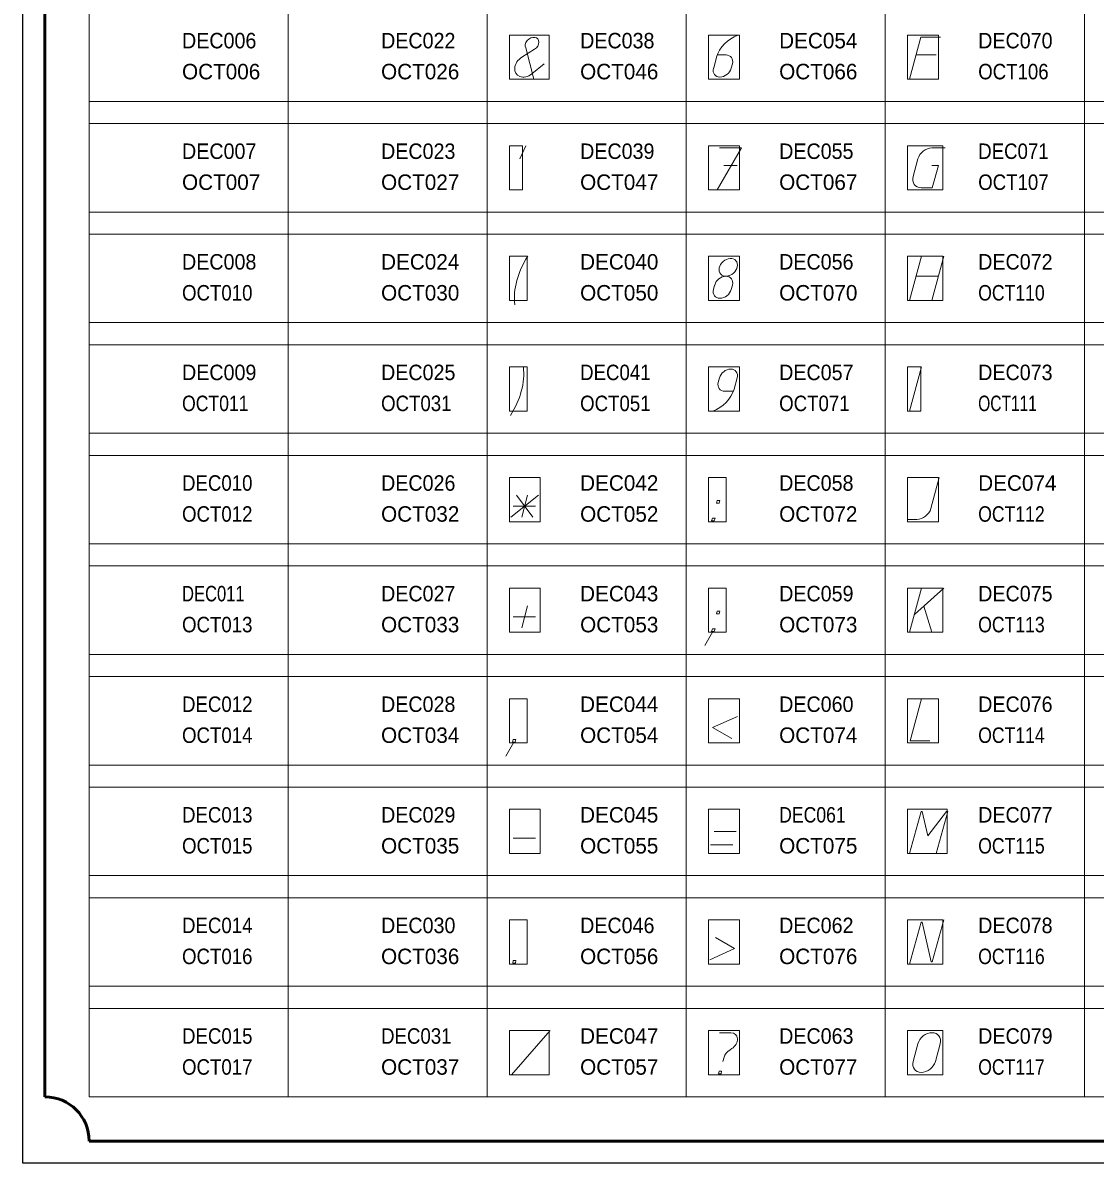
# Model space of a CAD drawing. Extents: x -200 to 7300, y -200 to 4800.
# Drawn here: x -200 to 2224, y -200 to 2378 of the extents above; entities that cross this region are included whole.
import ezdxf

# ---------------------------------------------------------------- set-up
doc = ezdxf.new("R2010")
doc.units = 0
doc.header["$LTSCALE"] = 14
for name, color, linetype, lineweight in [('1', 7, 'Continuous', 13), ('5', 7, 'Continuous', 40), ('6', 7, 'Continuous', 13), ('63', 7, 'Continuous', 13)]:
    doc.layers.add(name, color=color, linetype=linetype, lineweight=lineweight)
doc.layers.add('10', color=7, linetype='Continuous')
doc.layers.add('11', color=7, linetype='Continuous')

msp = doc.modelspace()

# ---------------------------------------------------------------- linework, layer by layer
at = {"layer": '1'}
for p, q in [((955, 2250), (937, 2321)), ((957, 2318), (928, 2300)), ((1368, 2300), (1362, 2275)), ((1370, 2305), (1390, 2305)), ((1865, 2305), (1820, 2305)), ((979, 2285), (950.8, 2262.3)), ((1404.2, 2285), (1401.6, 2275)), ((924, 2070), (937, 2100)), ((1885, 2095), (1855, 2095)), ((1823.6, 2070), (1812.9, 2030)), ((1385, 2055), (1415, 2055)), ((1832, 1850), (1805, 1750)), ((1882, 1850), (1855, 1750)), ((1820, 1805), (1870, 1805)), ((1364, 1785), (1361.6, 1775)), ((1404.3, 1785), (1401.6, 1775)), ((1832, 1600), (1805, 1500)), ((1372.3, 1565), (1375, 1575)), ((1408.3, 1550), (1415, 1575)), ((1407, 1545), (1387, 1545)), ((1853, 1280), (1872, 1350)), ((903, 1260), (966, 1310)), ((916, 1310), (953, 1260)), ((941, 1310), (928, 1260)), ((909, 1285), (959, 1285)), ((1801, 1255), (1821.3, 1255)), ((1832, 1100), (1805, 1000)), ((1882, 1100), (1816, 1040)), ((928, 1010), (941, 1060)), ((1837, 1059), (1855, 1000)), ((909, 1035), (959, 1035)), ((1363, 550), (1413, 550)), ((909, 535), (959, 535)), ((1355, 520), (1405, 520)), ((905, 0), (992, 100)), ((1375, 95), (1400, 95)), ((1399, 56), (1403, 59)), ((1823.8, 70), (1813, 30)), ((1873.8, 70), (1863.1, 30)), ((1383, 30), (1385.5, 39.3))]:
    msp.add_line(p, q, dxfattribs=at)
for points in [[(1875, 2345), (1830, 2345), (1805, 2250)], [(1375, 2095), (1425, 2095), (1370, 2000)], [(1831, 2005), (1856, 2005), (1870, 2055), (1855, 2055)], [(1360, 1002), (1357, 1002), (1359, 1008), (1365, 1008), (1363, 1002), (1360, 1002), (1342, 970)], [(1851, 755), (1806, 755), (1832, 850)], [(1416, 810), (1359, 785), (1403, 760)], [(910, 752), (907, 752), (909, 758), (915, 758), (913, 752), (910, 752), (892, 720)], [(1805, 500), (1831, 595), (1833, 595), (1846, 540), (1888, 595), (1891, 595), (1865, 500)], [(1805, 250), (1831, 345), (1833, 345), (1854, 255), (1856, 255), (1882, 350)], [(1366, 310), (1409, 285), (1353, 260)]]:
    msp.add_lwpolyline(points, dxfattribs=at)
for points in [[(1368, 1292), (1374, 1292), (1376, 1298), (1370, 1298)], [(1357, 1252), (1363, 1252), (1365, 1258), (1359, 1258)], [(1368, 1042), (1374, 1042), (1376, 1048), (1370, 1048)], [(908, 252), (914, 252), (915, 258), (909, 258)], [(1373, 2), (1379, 2), (1380, 8), (1374, 8)]]:
    msp.add_lwpolyline(points, close=True, dxfattribs=at)
for centre, major_axis, start_param, end_param in [((1423.85, 2297.95), (-48.32, -42.27), 4.2461946, 5.3948042), ((951.29, 2330), (-12.9, -11.29), 1.3623375, 6.0890323), ((937.9, 2280), (-21.5, -18.81), 4.5039301, 7.7874198), ((1384.24, 2285), (-17.2, -15.05), 2.2896327, 3.860429), ((1381.56, 2275), (17.2, 15.05), 2.2896328, 5.4312254), ((1848.64, 2070), (-21.5, -18.81), 3.860429, 5.4312252), ((1837.92, 2030), (21.5, 18.81), 2.2896328, 3.860429), ((1071.95, 1795), (133.39, 116.71), 1.9270883, 2.6521768), ((1384.27, 1785), (-17.2, -15.05), 2.2896326, 5.4312252), ((1381.59, 1775), (17.2, 15.05), 2.2896328, 5.4312254), ((771.96, 1545), (133.39, 116.71), 5.0686811, 5.7937695), ((1395.01, 1575), (-17.2, -15.05), 2.2896326, 5.4312252), ((1352.72, 1552.04), (48.32, 42.27), 4.2461945, 5.3948041), ((1392.33, 1565), (17.2, 15.05), 2.2896327, 3.860429), ((1827.97, 1280), (-21.5, -18.81), 0.7188363, 2.2896326), ((1395.1, 75), (-17.2, -15.05), 1.3623374, 3.860429), ((1848.8, 70), (-21.5, -18.81), 2.2896326, 5.4312252), ((1405.54, 39.3), (-17.2, -15.05), 4.4484316, 5.4312253), ((1838.1, 30), (21.5, 18.81), 2.2896328, 5.4312254)]:
    msp.add_ellipse(centre, major_axis=major_axis, ratio=0.765566, start_param=start_param, end_param=end_param, dxfattribs=at)
msp.add_ellipse((1394.99, 1825), major_axis=(-17.2, -15.05), ratio=0.765566, dxfattribs=at)
at = {"layer": '5', "lineweight": 53}
for p, q in [((-150, -50), (-150, 4650)), ((7150, -150), (-50, -150))]:
    msp.add_line(p, q, dxfattribs=at)
at = {"layer": '5', "lineweight": 25}
msp.add_lwpolyline([(-200, -200), (-200, 4800), (7300, 4800), (7300, -200)], close=True, dxfattribs=at)
at = {"layer": '5', "lineweight": 53}
msp.add_arc((-150, -150), 100, 0, 90, dxfattribs=at)
at = {"layer": '6'}
for p, q in [((-50, 3950), (-50, -50)), ((400, 3950), (400, -50)), ((850, 3950), (850, -50)), ((1300, 3950), (1300, -50)), ((1750, 3950), (1750, -50)), ((2200, 3950), (2200, -50)), ((-50, 2200), (7150, 2200)), ((-50, 2150), (7150, 2150)), ((-50, 1950), (7150, 1950)), ((-50, 1900), (7150, 1900)), ((-50, 1700), (7150, 1700)), ((-50, 1650), (7150, 1650)), ((-50, 1450), (7150, 1450)), ((-50, 1400), (7150, 1400)), ((-50, 1200), (7150, 1200)), ((-50, 1150), (7150, 1150)), ((-50, 950), (7150, 950)), ((-50, 900), (7150, 900)), ((-50, 700), (7150, 700)), ((-50, 650), (7150, 650)), ((-50, 450), (7150, 450)), ((-50, 400), (7150, 400)), ((-50, 200), (7150, 200)), ((-50, 150), (7150, 150)), ((-50, -50), (7150, -50))]:
    msp.add_line(p, q, dxfattribs=at)
at = {"layer": '63'}
for points in [[(900, 2250), (990, 2250), (990, 2350), (900, 2350)], [(1350, 2250), (1420, 2250), (1420, 2350), (1350, 2350)], [(1800, 2250), (1870, 2250), (1870, 2350), (1800, 2350)], [(900, 2000), (930, 2000), (930, 2100), (900, 2100)], [(1350, 2000), (1420, 2000), (1420, 2100), (1350, 2100)], [(1800, 2000), (1880, 2000), (1880, 2100), (1800, 2100)], [(900, 1750), (940, 1750), (940, 1850), (900, 1850)], [(1350, 1750), (1420, 1750), (1420, 1850), (1350, 1850)], [(1800, 1750), (1880, 1750), (1880, 1850), (1800, 1850)], [(900, 1500), (940, 1500), (940, 1600), (900, 1600)], [(1350, 1500), (1420, 1500), (1420, 1600), (1350, 1600)], [(1800, 1500), (1830, 1500), (1830, 1600), (1800, 1600)], [(900, 1250), (970, 1250), (970, 1350), (900, 1350)], [(1350, 1250), (1390, 1250), (1390, 1350), (1350, 1350)], [(1800, 1250), (1870, 1250), (1870, 1350), (1800, 1350)], [(900, 1000), (970, 1000), (970, 1100), (900, 1100)], [(1350, 1000), (1390, 1000), (1390, 1100), (1350, 1100)], [(1800, 1000), (1880, 1000), (1880, 1100), (1800, 1100)], [(900, 750), (940, 750), (940, 850), (900, 850)], [(1350, 750), (1420, 750), (1420, 850), (1350, 850)], [(1800, 750), (1870, 750), (1870, 850), (1800, 850)], [(900, 500), (970, 500), (970, 600), (900, 600)], [(1350, 500), (1420, 500), (1420, 600), (1350, 600)], [(1800, 500), (1890, 500), (1890, 600), (1800, 600)], [(900, 250), (940, 250), (940, 350), (900, 350)], [(1350, 250), (1420, 250), (1420, 350), (1350, 350)], [(1800, 250), (1880, 250), (1880, 350), (1800, 350)], [(900, 0), (990, 0), (990, 100), (900, 100)], [(1350, 0), (1420, 0), (1420, 100), (1350, 100)], [(1800, 0), (1880, 0), (1880, 100), (1800, 100)]]:
    msp.add_lwpolyline(points, close=True, dxfattribs=at)

# ---------------------------------------------------------------- texts
at = {"layer": '10'}
for s, width, p in [('DEC006', 0.95, (160, 2320)), ('DEC022', 0.95, (610, 2320)), ('DEC038', 0.95, (1060, 2320)), ('DEC070', 0.95, (1960, 2320)), ('DEC007', 0.95, (160, 2070)), ('DEC023', 0.95, (610, 2070)), ('DEC039', 0.95, (1060, 2070)), ('DEC055', 0.95, (1510, 2070)), ('DEC071', 0.9, (1960, 2070)), ('DEC008', 0.95, (160, 1820)), ('DEC056', 0.95, (1510, 1820)), ('DEC072', 0.95, (1960, 1820)), ('DEC009', 0.95, (160, 1570)), ('DEC025', 0.95, (610, 1570)), ('DEC041', 0.9, (1060, 1570)), ('DEC057', 0.95, (1510, 1570)), ('DEC073', 0.95, (1960, 1570)), ('DEC010', 0.9, (160, 1320)), ('DEC026', 0.95, (610, 1320)), ('DEC058', 0.95, (1510, 1320)), ('DEC011', 0.8, (160, 1070)), ('DEC027', 0.95, (610, 1070)), ('DEC059', 0.95, (1510, 1070)), ('DEC075', 0.95, (1960, 1070)), ('DEC012', 0.9, (160, 820)), ('DEC028', 0.95, (610, 820)), ('DEC060', 0.95, (1510, 820)), ('DEC076', 0.95, (1960, 820)), ('DEC013', 0.9, (160, 570)), ('DEC029', 0.95, (610, 570)), ('DEC061', 0.85, (1510, 570)), ('DEC077', 0.95, (1960, 570)), ('DEC014', 0.9, (160, 320)), ('DEC030', 0.95, (610, 320)), ('DEC046', 0.95, (1060, 320)), ('DEC062', 0.95, (1510, 320)), ('DEC078', 0.95, (1960, 320)), ('DEC015', 0.9, (160, 70)), ('DEC031', 0.9, (610, 70)), ('DEC063', 0.95, (1510, 70)), ('DEC079', 0.95, (1960, 70))]:
    msp.add_text(s, height=35, dxfattribs=dict(at, width=width)).set_placement(p)
for s, p in [('DEC054', (1510, 2320)), ('DEC024', (610, 1820)), ('DEC040', (1060, 1820)), ('DEC042', (1060, 1320)), ('DEC074', (1960, 1320)), ('DEC043', (1060, 1070)), ('DEC044', (1060, 820)), ('DEC045', (1060, 570)), ('DEC047', (1060, 70))]:
    msp.add_text(s, height=35, dxfattribs=at).set_placement(p)
at = {"layer": '11'}
for s, p in [('OCT006', (160, 2250)), ('OCT026', (610, 2250)), ('OCT046', (1060, 2250)), ('OCT066', (1510, 2250)), ('OCT007', (160, 2000)), ('OCT027', (610, 2000)), ('OCT047', (1060, 2000)), ('OCT067', (1510, 2000)), ('OCT030', (610, 1750)), ('OCT050', (1060, 1750)), ('OCT070', (1510, 1750)), ('OCT032', (610, 1250)), ('OCT052', (1060, 1250)), ('OCT072', (1510, 1250)), ('OCT033', (610, 1000)), ('OCT053', (1060, 1000)), ('OCT073', (1510, 1000)), ('OCT034', (610, 750)), ('OCT054', (1060, 750)), ('OCT074', (1510, 750)), ('OCT035', (610, 500)), ('OCT055', (1060, 500)), ('OCT075', (1510, 500)), ('OCT036', (610, 250)), ('OCT056', (1060, 250)), ('OCT076', (1510, 250)), ('OCT037', (610, 0)), ('OCT057', (1060, 0)), ('OCT077', (1510, 0))]:
    msp.add_text(s, height=35, dxfattribs=at).set_placement(p)
for s, width, p in [('OCT106', 0.9, (1960, 2250)), ('OCT107', 0.9, (1960, 2000)), ('OCT010', 0.9, (160, 1750)), ('OCT110', 0.85, (1960, 1750)), ('OCT011', 0.85, (160, 1500)), ('OCT031', 0.9, (610, 1500)), ('OCT051', 0.9, (1060, 1500)), ('OCT071', 0.9, (1510, 1500)), ('OCT111', 0.75, (1960, 1500)), ('OCT012', 0.9, (160, 1250)), ('OCT112', 0.85, (1960, 1250)), ('OCT013', 0.9, (160, 1000)), ('OCT113', 0.85, (1960, 1000)), ('OCT014', 0.9, (160, 750)), ('OCT114', 0.85, (1960, 750)), ('OCT015', 0.9, (160, 500)), ('OCT115', 0.85, (1960, 500)), ('OCT016', 0.9, (160, 250)), ('OCT116', 0.85, (1960, 250)), ('OCT017', 0.9, (160, 0)), ('OCT117', 0.85, (1960, 0))]:
    msp.add_text(s, height=35, dxfattribs=dict(at, width=width)).set_placement(p)

doc.saveas('drawing.dxf')
